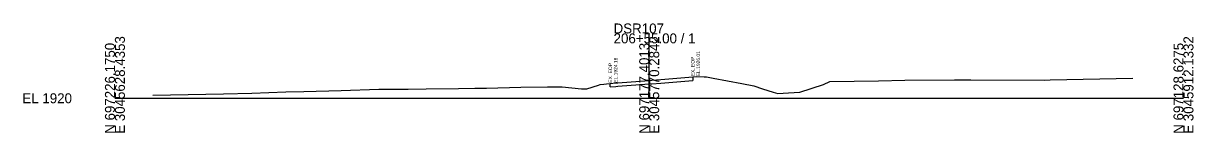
# Model space of a CAD drawing. Extents: x -26 to 19003, y -31 to 24541.
# Drawn here: x 1974.3 to 2302.8, y 12990.3 to 13021.1 of the extents above; entities that cross this region are included whole.
import ezdxf

# ---------------------------------------------------------------- set-up
doc = ezdxf.new("R2010")
doc.units = 0
for name, color, linetype in [('DESIGN - SHEET - Light Grid', 7, 'Continuous'), ('SURVEY - GROUND - Existing Pavement Layer', 7, 'Continuous'), ('SURVEY - GROUND - Existing Pavement Text', 7, 'Continuous'), ('SURVEY - GROUND - Top of Ground', 7, 'Continuous')]:
    doc.layers.add(name, color=color, linetype=linetype)

msp = doc.modelspace()

# ---------------------------------------------------------------- linework, layer by layer
at = {"layer": 'DESIGN - SHEET - Light Grid'}
for p, q in [((2150, 13000), (2150, 13018.26)), ((2000, 13000), (2150, 13000)), ((2150, 13000), (2300, 13000))]:
    msp.add_line(p, q, dxfattribs=at)
at = {"layer": 'SURVEY - GROUND - Existing Pavement Layer'}
for p, q in [((2139.08, 13003.18), (2139.08, 13004.18)), ((2140.62, 13003.3), (2141.22, 13003.37)), ((2141.22, 13003.37), (2150, 13004.04)), ((2150, 13004.04), (2150.7, 13004.09)), ((2150.7, 13004.09), (2153.27, 13004.29)), ((2153.27, 13004.29), (2162.24, 13005.01)), ((2162.24, 13006.01), (2162.24, 13005.01)), ((2139.08, 13003.18), (2140.62, 13003.3))]:
    msp.add_line(p, q, dxfattribs=at)
at = {"layer": 'SURVEY - GROUND - Top of Ground'}
msp.add_lwpolyline([(2010.65, 13000.89), (2030.5, 13001.29), (2038.41, 13001.46), (2048.02, 13001.85), (2053.08, 13001.94), (2063.54, 13002.16), (2074.07, 13002.53), (2079.3, 13002.52), (2081.52, 13002.56), (2082.29, 13002.57), (2087.42, 13002.65), (2096.43, 13002.78), (2101.03, 13002.83), (2104.3, 13002.87), (2113.98, 13003.09), (2121.41, 13003.21), (2124.06, 13003.17), (2125.6, 13003.18), (2131.01, 13002.61), (2131.8, 13002.63), (2132.46, 13002.65), (2135.75, 13003.64), (2136.27, 13003.89), (2137.25, 13003.99), (2138.03, 13004.07), (2139.08, 13004.18), (2140.62, 13004.3), (2141.22, 13004.37), (2150, 13005.04), (2150.7, 13005.09), (2153.27, 13005.29), (2162.24, 13006.01), (2163.33, 13006.09), (2165.45, 13006.02), (2166.11, 13006.02), (2167.96, 13005.62), (2176.03, 13004.13), (2179.33, 13003.5), (2181.8, 13002.64), (2184.79, 13001.74), (2186.11, 13001.37), (2189.09, 13001.49), (2192.33, 13001.68), (2198.9, 13003.91), (2200.73, 13004.7), (2214.42, 13004.9), (2221.74, 13005.06), (2235.74, 13005.18), (2240.27, 13005.21), (2260.86, 13005.11), (2262.6, 13005.15), (2285.74, 13005.68)], dxfattribs=at)

# ---------------------------------------------------------------- texts
at = {"layer": 'DESIGN - SHEET - Light Grid'}
for s, p in [('DSR107', (2140, 13018.26)), ('206+55.00 / 1', (2140, 13015.46)), ('EL 1920', (1974, 12998.6))]:
    msp.add_text(s, height=2.8, dxfattribs=at).set_placement(p)
for s, p in [('E 3045628.4353', (2002.8, 12990)), ('E 3045770.2842', (2152.8, 12990)), ('E 3045912.1332', (2302.8, 12990)), ('N 697226.1750', (2000, 12990)), ('N 697177.4013', (2150, 12990)), ('N 697128.6275', (2300, 12990))]:
    msp.add_text(s, height=2.8, rotation=90, dxfattribs=at).set_placement(p)
at = {"layer": 'SURVEY - GROUND - Existing Pavement Text'}
for s, p in [('EL.1924.18', (2141.08, 13004.38)), ('EX. EOP', (2162.74, 13006.21)), ('EL.1926.01', (2164.24, 13006.21)), ('EX. EOP', (2139.58, 13004.38))]:
    msp.add_text(s, height=1, rotation=90, dxfattribs=at).set_placement(p)

doc.saveas('drawing.dxf')
